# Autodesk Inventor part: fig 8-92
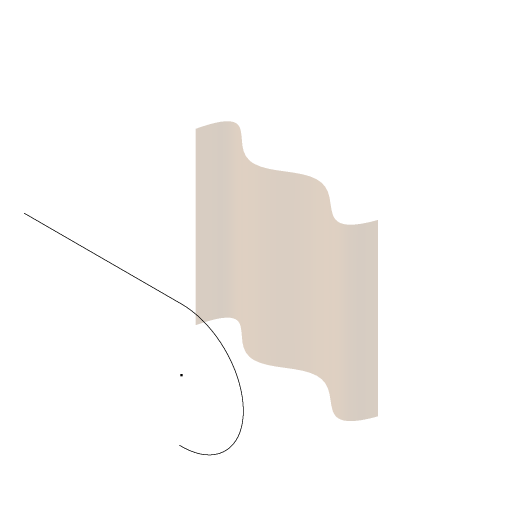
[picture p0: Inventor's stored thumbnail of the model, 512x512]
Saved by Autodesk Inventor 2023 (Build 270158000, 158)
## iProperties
Part Number: fig 8-92
Document SubType Name: Modeling
Created: 2003-08
Designer: Owner
Manufacturer: Standard
Standards Organization: Custom
Density: 1 g/cm^3
Material: Generic
Appearance: Default
Control State: 0
Master: False
Checked Out: False
Shininess: 64.0
Length Units: 11269
Angle Units: 11279
Time Units: 11290
Mass Units: 11283
Length Display Precision: 3
Angle Display Precision: 2
Compacted: True
Density: 0.0
Volumn: 0.0
Area: 0.0
PropertySet Name: Model Information
Author: Owner
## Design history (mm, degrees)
sketch "Sketch1"
  geometry: 7 further points
  constraints: 7 other
  dimensions: "d0" = 80 horizontal distance of point (40, 1.742) point (-40, -4.065); "d1" = 40 horizontal distance of point (0, 0) point (-40, -4.065)
extrude_surface "ExtrusionSrf1" sketch "Sketch1" dims "d2" = 80, "d3" = 0
sketch "Sketch2"
  geometry: L1 (40, 0)-(40, -40) reference; L2 (-40, 0)-(-40, -40) reference; 7 further points
  constraints: 2 point on line, 7 other
extrude_surface "ExtrusionSrf2" sketch "Sketch2" dims "d4" = 80, "d5" = 0
workplane "Work Plane1"
sketch "Sketch4"
  geometry: L1 (70.027, 16.004)-(-4, 16.004); A1 r 29.004 centre (-4, -13) between (-4, 16.004) and (-2.981, -41.986)
  constraints: 2 end point, 2 point on circle, 1 centre point, 1 horizontal, 1 tangent
body "Srf1"
body "Srf2"
other parameters: "d6" = -54.75
